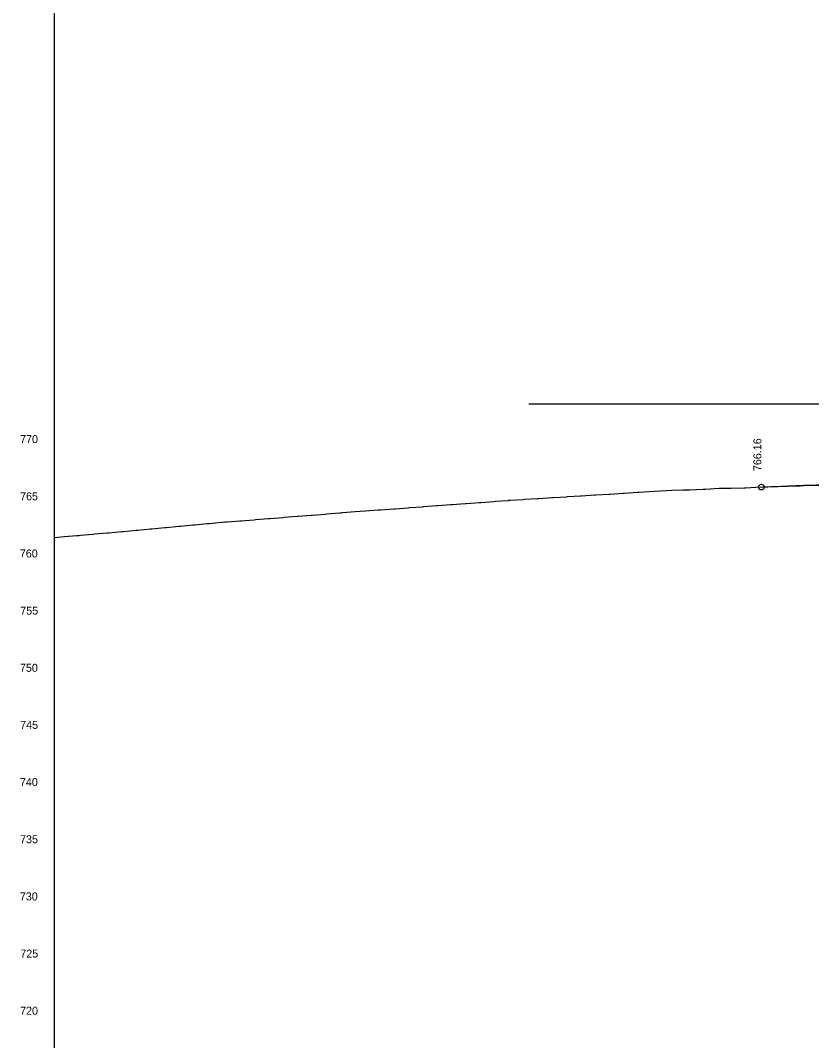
# Model space of a CAD drawing. Extents: x 40 to 3352, y -2509 to 347.
# Drawn here: x 40.5 to 317.3, y -1437.7 to -1080.7 of the extents above; entities that cross this region are included whole.
import ezdxf

# ---------------------------------------------------------------- set-up
doc = ezdxf.new("R2010")
doc.units = 0
for name, color, linetype in [('GK_Cells', 7, 'Continuous'), ('PF_P_Grade_Line', 7, 'Continuous'), ('PF_P_Sta_Elev_Text', 7, 'Continuous'), ('PF_P_Text', 7, 'Continuous'), ('PF_X_Ground_Line', 7, 'Continuous')]:
    doc.layers.add(name, color=color, linetype=linetype)

msp = doc.modelspace()

# ---------------------------------------------------------------- linework, layer by layer
at = {"layer": 'GK_Cells'}
msp.add_line((52.42, -1508.6), (52.42, -508.6), dxfattribs=at)
at = {"layer": 'PF_P_Grade_Line'}
msp.add_spline([(299.73, -1243.96), (308.97, -1243.58), (320.29, -1243.13), (331.61, -1242.71), (342.93, -1242.31), (354.25, -1241.94), (365.57, -1241.59), (376.89, -1241.26), (388.21, -1240.96), (399.53, -1240.68), (410.85, -1240.42), (422.17, -1240.18), (433.49, -1239.97), (444.81, -1239.79), (456.13, -1239.62), (467.45, -1239.48), (478.77, -1239.36), (490.09, -1239.27), (501.41, -1239.2), (512.73, -1239.15), (524.05, -1239.13), (535.37, -1239.13), (546.69, -1239.15), (558.01, -1239.2), (569.33, -1239.27), (580.65, -1239.36), (591.97, -1239.48), (603.29, -1239.62), (614.61, -1239.78), (625.93, -1239.97), (637.25, -1240.18), (648.57, -1240.41), (659.89, -1240.67), (671.21, -1240.95), (682.53, -1241.26), (693.85, -1241.58), (705.17, -1241.93), (705.49, -1241.94)], degree=3, dxfattribs=at)
at = {"layer": 'PF_P_Text'}
msp.add_line((218.41, -1214.82), (784.41, -1214.82), dxfattribs=at)
msp.add_circle((299.73, -1243.96), 1, dxfattribs=at)
at = {"layer": 'PF_X_Ground_Line'}
for points in [[(52.42, -1261.6), (54.77, -1261.4), (55.98, -1261.29), (60.26, -1260.9), (61.03, -1260.89), (61.59, -1260.84), (66.03, -1260.43), (66.59, -1260.38), (71.03, -1259.97), (71.58, -1259.92), (76.03, -1259.51), (76.57, -1259.46), (81.03, -1259.05), (81.57, -1259), (86.02, -1258.59), (86.56, -1258.54), (91.02, -1258.13), (91.55, -1258.08), (96.02, -1257.67), (96.55, -1257.62), (101.02, -1257.21), (101.54, -1257.16), (106.02, -1256.75), (106.54, -1256.7), (111.02, -1256.29), (111.17, -1256.27), (112.29, -1256.17), (112.8, -1256.12), (117.29, -1255.77), (117.79, -1255.73), (122.29, -1255.38), (122.78, -1255.33), (127.29, -1254.98), (127.77, -1254.94), (132.29, -1254.59), (132.76, -1254.55), (137.29, -1254.19), (137.75, -1254.15), (142.29, -1253.8), (142.74, -1253.76), (147.29, -1253.4), (147.73, -1253.36), (152.29, -1253.01), (152.72, -1252.97), (153.17, -1252.9), (157.64, -1252.55), (161.19, -1252.28), (165.69, -1251.94), (166.16, -1251.94), (166.58, -1251.91), (171.16, -1251.57), (171.58, -1251.54), (176.15, -1251.2), (176.59, -1251.17), (181.15, -1250.83), (181.59, -1250.8), (186.15, -1250.46), (186.6, -1250.43), (191.15, -1250.09), (191.6, -1250.06), (196.14, -1249.72), (196.61, -1249.69), (201.14, -1249.35), (201.61, -1249.31), (206.14, -1248.98), (206.62, -1248.94), (211.13, -1248.61), (211.31, -1248.59), (211.87, -1248.55), (216.39, -1248.27), (216.87, -1248.24), (221.39, -1247.96), (221.87, -1247.94), (226.4, -1247.65), (226.87, -1247.63), (231.41, -1247.34), (231.86, -1247.32), (236.42, -1247.03), (236.86, -1247.01), (241.42, -1246.73), (241.86, -1246.7), (246.43, -1246.42), (246.86, -1246.39), (251.44, -1246.11), (251.86, -1246.08), (256.45, -1245.8), (256.86, -1245.77), (258.62, -1245.6), (262.5, -1245.35), (264.46, -1245.23), (268.38, -1245.09), (272.33, -1244.95), (274.33, -1244.94), (274.71, -1244.92), (279.33, -1244.75), (280.22, -1244.66), (284.93, -1244.39), (285.73, -1244.36), (286.56, -1244.33), (289.14, -1244.34), (293.62, -1244.18)], [(293.62, -1244.18), (294.33, -1244.19), (297.76, -1243.98), (300.36, -1243.89), (303, -1243.8), (304.55, -1243.81), (308.92, -1243.65), (313.31, -1243.49), (314.59, -1243.41), (319.01, -1243.35), (320.31, -1243.31), (320.45, -1243.3), (321.51, -1243.22), (323.87, -1242.99), (324.82, -1242.95), (326.99, -1242.89), (337.77, -1242.87), (341.71, -1242.92), (345.06, -1242.73)]]:
    msp.add_lwpolyline(points, dxfattribs=at)

# ---------------------------------------------------------------- texts
at = {"layer": 'PF_P_Sta_Elev_Text'}
for s, p in [('770', (40.43, -1228.6)), ('770', (40.43, -1228.6)), ('765', (40.43, -1248.6)), ('765', (40.43, -1248.6)), ('760', (40.34, -1268.6)), ('760', (40.34, -1268.6)), ('755', (40.47, -1288.6)), ('755', (40.47, -1288.6)), ('750', (40.38, -1308.6)), ('750', (40.38, -1308.6)), ('745', (40.45, -1328.6)), ('745', (40.45, -1328.6)), ('740', (40.36, -1348.6)), ('740', (40.36, -1348.6)), ('735', (40.43, -1368.6)), ('735', (40.43, -1368.6)), ('730', (40.34, -1388.6)), ('730', (40.34, -1388.6)), ('725', (40.51, -1408.6)), ('725', (40.51, -1408.6)), ('720', (40.43, -1428.6)), ('720', (40.43, -1428.6))]:
    msp.add_text(s, height=2.8, dxfattribs=at).set_placement(p)
at = {"layer": 'PF_P_Text'}
msp.add_text('766.16', height=2.8, rotation=90, dxfattribs=at).set_placement((299.73, -1238.36))

doc.saveas('drawing.dxf')
